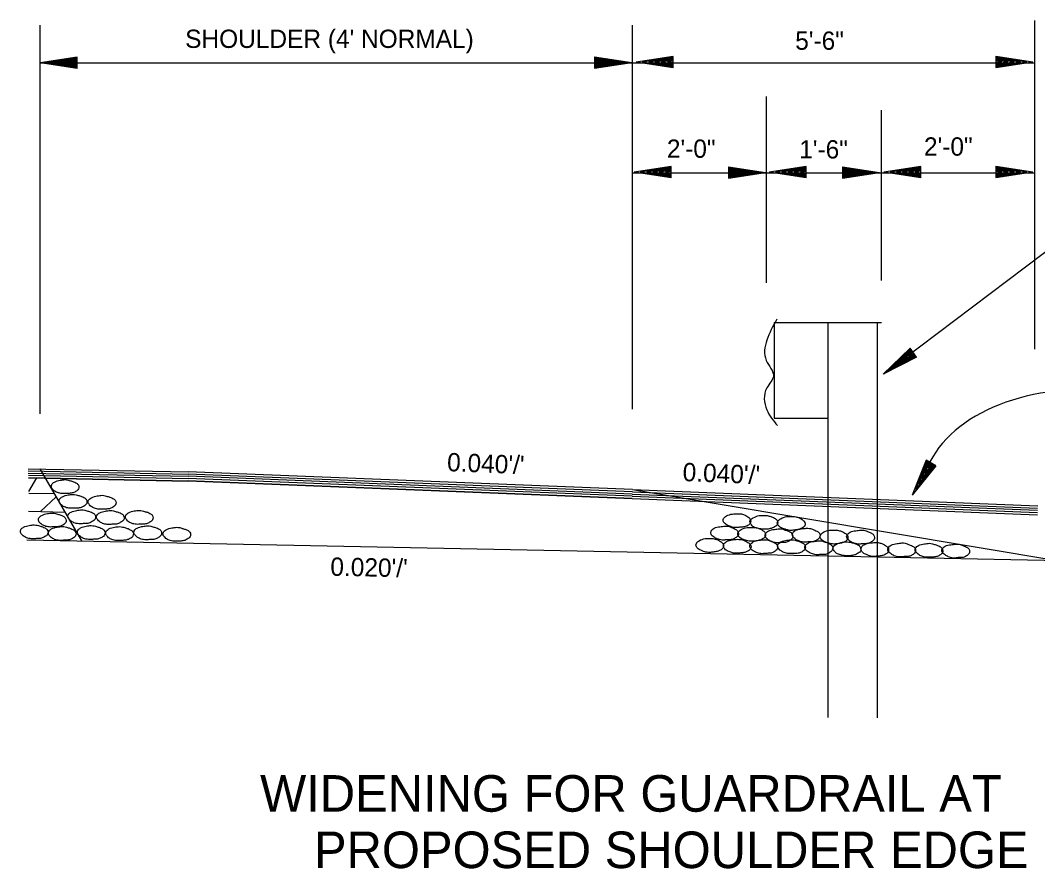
# Model space of a CAD drawing. Extents: x 3314 to 1767681, y -207 to 581440.
# Drawn here: x 3447.3 to 3514, y -206.8 to -151.2 of the extents above; entities that cross this region are included whole.
import ezdxf

# ---------------------------------------------------------------- set-up
doc = ezdxf.new("R2010")
doc.units = 0
doc.layers.add('Default', color=7, linetype='Continuous')

msp = doc.modelspace()

# ---------------------------------------------------------------- linework, layer by layer
at = {"layer": 'Default'}
for p, q in [((3448.572, -177.002), (3448.572, -151.494)), ((3487.452, -176.688), (3487.452, -151.494)), ((3513.862, -172.76), (3513.862, -151.181)), ((3484.969, -153.574), (3487.404, -153.943)), ((3484.969, -153.574), (3484.969, -154.308)), ((3490.125, -153.555), (3487.69, -153.919)), ((3490.125, -154.288), (3490.125, -153.555)), ((3511.305, -153.53), (3513.74, -153.9)), ((3511.305, -153.53), (3511.305, -154.264)), ((3451.007, -153.598), (3448.572, -153.963)), ((3448.572, -153.963), (3513.862, -153.963)), ((3451.007, -154.332), (3448.572, -153.963)), ((3451.007, -153.662), (3448.981, -153.963)), ((3451.007, -154.269), (3448.981, -153.963)), ((3451.007, -153.725), (3449.399, -153.963)), ((3451.007, -154.206), (3449.399, -153.963)), ((3451.007, -153.783), (3449.807, -153.963)), ((3451.007, -154.148), (3449.807, -153.963)), ((3451.007, -153.846), (3450.215, -153.963)), ((3451.007, -154.084), (3450.215, -153.963)), ((3451.007, -153.909), (3450.623, -153.963)), ((3451.007, -154.021), (3450.623, -153.963)), ((3451.007, -154.332), (3451.007, -153.598)), ((3484.969, -153.637), (3486.995, -153.943)), ((3484.969, -153.7), (3486.578, -153.943)), ((3484.969, -153.759), (3486.169, -153.943)), ((3484.969, -153.822), (3485.761, -153.943)), ((3484.969, -153.885), (3485.353, -153.943)), ((3484.969, -154.308), (3487.404, -153.943)), ((3484.969, -154.06), (3485.761, -153.943)), ((3484.969, -154.182), (3486.578, -153.943)), ((3484.969, -154.245), (3486.995, -153.943)), ((3484.969, -154.123), (3486.169, -153.943)), ((3484.969, -153.997), (3485.353, -153.943)), ((3490.125, -154.288), (3487.69, -153.919)), ((3490.125, -153.618), (3488.099, -153.919)), ((3490.125, -154.225), (3488.099, -153.919)), ((3490.125, -153.681), (3488.517, -153.919)), ((3490.125, -154.162), (3488.517, -153.919)), ((3490.125, -153.739), (3488.925, -153.919)), ((3490.125, -154.104), (3488.925, -153.919)), ((3490.125, -153.802), (3489.333, -153.919)), ((3490.125, -154.041), (3489.333, -153.919)), ((3490.125, -153.866), (3489.741, -153.919)), ((3490.125, -153.977), (3489.741, -153.919)), ((3511.305, -153.593), (3513.332, -153.9)), ((3511.305, -153.657), (3512.914, -153.9)), ((3511.305, -153.715), (3512.506, -153.9)), ((3511.305, -153.778), (3512.097, -153.9)), ((3511.305, -153.841), (3511.689, -153.9)), ((3511.305, -154.264), (3513.74, -153.9)), ((3511.305, -154.016), (3512.097, -153.9)), ((3511.305, -154.138), (3512.914, -153.9)), ((3511.305, -154.201), (3513.332, -153.9)), ((3511.305, -154.079), (3512.506, -153.9)), ((3511.305, -153.953), (3511.689, -153.9)), ((3496.254, -168.395), (3496.254, -156.174)), ((3503.801, -168.237), (3503.801, -157.064)), ((3489.994, -160.777), (3487.559, -161.141)), ((3489.994, -160.84), (3487.967, -161.141)), ((3489.994, -160.903), (3488.385, -161.141)), ((3489.994, -161.51), (3489.994, -160.777)), ((3493.751, -160.801), (3496.186, -161.17)), ((3493.751, -160.801), (3493.751, -161.535)), ((3493.751, -160.864), (3495.778, -161.17)), ((3498.864, -160.777), (3496.429, -161.141)), ((3498.864, -160.84), (3496.837, -161.141)), ((3498.864, -160.903), (3497.255, -161.141)), ((3498.864, -161.51), (3498.864, -160.777)), ((3501.23, -160.796), (3503.665, -161.165)), ((3501.23, -160.796), (3501.23, -161.53)), ((3501.23, -160.859), (3503.257, -161.165)), ((3506.387, -160.772), (3503.952, -161.136)), ((3506.387, -160.835), (3504.36, -161.136)), ((3506.387, -160.898), (3504.778, -161.136)), ((3506.387, -161.506), (3506.387, -160.772)), ((3511.305, -160.757), (3513.74, -161.126)), ((3511.305, -160.757), (3511.305, -161.491)), ((3511.305, -160.82), (3513.332, -161.126)), ((3511.305, -160.883), (3512.914, -161.126)), ((3487.452, -161.185), (3513.862, -161.185)), ((3489.994, -161.51), (3487.559, -161.141)), ((3489.994, -161.447), (3487.967, -161.141)), ((3489.994, -161.384), (3488.385, -161.141)), ((3489.994, -160.961), (3488.794, -161.141)), ((3489.994, -161.326), (3488.794, -161.141)), ((3489.994, -161.024), (3489.202, -161.141)), ((3489.994, -161.263), (3489.202, -161.141)), ((3489.994, -161.088), (3489.61, -161.141)), ((3489.994, -161.199), (3489.61, -161.141)), ((3493.751, -160.927), (3495.36, -161.17)), ((3493.751, -160.986), (3494.951, -161.17)), ((3493.751, -161.049), (3494.543, -161.17)), ((3493.751, -161.112), (3494.135, -161.17)), ((3493.751, -161.535), (3496.186, -161.17)), ((3493.751, -161.287), (3494.543, -161.17)), ((3493.751, -161.408), (3495.36, -161.17)), ((3493.751, -161.472), (3495.778, -161.17)), ((3493.751, -161.35), (3494.951, -161.17)), ((3493.751, -161.224), (3494.135, -161.17)), ((3498.864, -161.51), (3496.429, -161.141)), ((3498.864, -161.447), (3496.837, -161.141)), ((3498.864, -161.384), (3497.255, -161.141)), ((3498.864, -160.961), (3497.663, -161.141)), ((3498.864, -161.326), (3497.663, -161.141)), ((3498.864, -161.024), (3498.071, -161.141)), ((3498.864, -161.263), (3498.071, -161.141)), ((3498.864, -161.088), (3498.48, -161.141)), ((3498.864, -161.199), (3498.48, -161.141)), ((3501.23, -160.922), (3502.839, -161.165)), ((3501.23, -160.981), (3502.431, -161.165)), ((3501.23, -161.044), (3502.023, -161.165)), ((3501.23, -161.107), (3501.614, -161.165)), ((3501.23, -161.53), (3503.665, -161.165)), ((3501.23, -161.282), (3502.023, -161.165)), ((3501.23, -161.404), (3502.839, -161.165)), ((3501.23, -161.467), (3503.257, -161.165)), ((3501.23, -161.345), (3502.431, -161.165)), ((3501.23, -161.219), (3501.614, -161.165)), ((3506.387, -161.506), (3503.952, -161.136)), ((3506.387, -161.442), (3504.36, -161.136)), ((3506.387, -161.379), (3504.778, -161.136)), ((3506.387, -160.956), (3505.186, -161.136)), ((3506.387, -161.321), (3505.186, -161.136)), ((3506.387, -161.02), (3505.595, -161.136)), ((3506.387, -161.258), (3505.595, -161.136)), ((3506.387, -161.083), (3506.003, -161.136)), ((3506.387, -161.195), (3506.003, -161.136)), ((3511.305, -160.942), (3512.506, -161.126)), ((3511.305, -161.005), (3512.097, -161.126)), ((3511.305, -161.068), (3511.689, -161.126)), ((3511.305, -161.491), (3513.74, -161.126)), ((3511.305, -161.243), (3512.097, -161.126)), ((3511.305, -161.365), (3512.914, -161.126)), ((3511.305, -161.428), (3513.332, -161.126)), ((3511.305, -161.306), (3512.506, -161.126)), ((3511.305, -161.18), (3511.689, -161.126)), ((3503.962, -174.355), (3517.652, -164.008)), ((3496.759, -170.997), (3496.759, -177.286)), ((3496.759, -170.997), (3503.801, -170.997)), ((3500.283, -170.997), (3500.283, -196.911)), ((3503.519, -171.026), (3503.519, -196.935)), ((3505.689, -172.693), (3503.899, -174.383)), ((3505.728, -172.74), (3504.231, -174.155)), ((3505.766, -172.799), (3504.585, -173.903)), ((3505.791, -172.849), (3504.914, -173.675)), ((3505.828, -172.891), (3505.245, -173.442)), ((3506.102, -173.286), (3505.689, -172.693)), ((3506.102, -173.286), (3503.899, -174.383)), ((3506.073, -173.241), (3504.231, -174.155)), ((3506.029, -173.187), (3504.585, -173.903)), ((3505.995, -173.136), (3504.914, -173.675)), ((3505.956, -173.082), (3505.245, -173.442)), ((3505.862, -172.944), (3505.582, -173.207)), ((3505.932, -173.027), (3505.582, -173.207)), ((3496.759, -177.286), (3500.283, -177.286)), ((3506.722, -180.037), (3505.818, -182.331)), ((3506.771, -180.076), (3506.022, -181.976)), ((3506.829, -180.105), (3506.231, -181.611)), ((3506.878, -180.134), (3506.431, -181.266)), ((3506.936, -180.163), (3506.64, -180.907)), ((3507.354, -180.406), (3506.722, -180.037)), ((3506.994, -180.197), (3506.849, -180.557)), ((3507.087, -180.251), (3506.849, -180.557)), ((3447.79, -180.591), (3458.292, -180.8)), ((3447.79, -180.737), (3458.292, -180.946)), ((3447.795, -180.882), (3458.292, -181.091)), ((3451.304, -185.329), (3448.572, -180.607)), ((3487.452, -181.966), (3458.292, -180.8)), ((3487.452, -182.112), (3458.292, -180.946)), ((3507.354, -180.406), (3505.818, -182.331)), ((3507.305, -180.372), (3506.022, -181.976)), ((3507.242, -180.348), (3506.231, -181.611)), ((3507.194, -180.314), (3506.431, -181.266)), ((3507.14, -180.285), (3506.64, -180.907)), ((3447.8, -181.028), (3458.292, -181.237)), ((3447.804, -181.174), (3458.283, -181.383)), ((3447.804, -181.193), (3458.292, -181.402)), ((3447.824, -182.078), (3448.349, -181.198)), ((3487.433, -182.549), (3458.273, -181.383)), ((3487.443, -182.258), (3458.283, -181.091)), ((3487.443, -182.404), (3458.283, -181.237)), ((3487.433, -182.569), (3458.292, -181.402)), ((3447.829, -182.195), (3449.51, -182.229)), ((3487.439, -182.258), (3514.038, -183.322)), ((3487.444, -182.112), (3514.043, -183.176)), ((3487.452, -181.966), (3514.051, -183.031)), ((3487.452, -181.966), (3534.38, -189.791)), ((3448.592, -183.405), (3449.625, -182.428)), ((3487.428, -182.549), (3514.027, -183.614)), ((3487.433, -182.404), (3514.032, -183.468)), ((3447.804, -183.389), (3450.209, -183.437)), ((3447.694, -185.256), (3525.399, -186.802))]:
    msp.add_line(p, q, dxfattribs=at)
msp.add_ellipse((3518.439, -183.401), major_axis=(-12.01, 1.466), ratio=0.655798, start_param=4.712389, end_param=6.093533, dxfattribs=at)
for points in [[(3496.929, -170.793), (3496.268, -172.159), (3496.234, -173.49), (3496.711, -174.516), (3496.268, -175.293), (3496.268, -176.727), (3496.968, -177.762)], [(3450.207, -181.312), (3449.886, -181.351), (3449.517, -181.467), (3449.332, -181.632), (3449.303, -181.749), (3449.39, -181.943), (3449.497, -182.041), (3449.711, -182.157), (3450.022, -182.225), (3450.178, -182.225), (3450.421, -182.216), (3450.683, -182.186), (3450.897, -182.099), (3451.091, -181.924), (3451.121, -181.807), (3451.062, -181.632), (3450.916, -181.516), (3450.771, -181.448), (3450.557, -181.38), (3450.411, -181.341), (3450.207, -181.312)], [(3450.735, -182.277), (3450.414, -182.316), (3450.045, -182.433), (3449.851, -182.598), (3449.821, -182.715), (3449.909, -182.909), (3450.016, -183.006), (3450.23, -183.123), (3450.541, -183.191), (3450.706, -183.191), (3450.949, -183.181), (3451.211, -183.152), (3451.415, -183.065), (3451.62, -182.89), (3451.649, -182.773), (3451.59, -182.598), (3451.445, -182.481), (3451.299, -182.413), (3451.075, -182.345), (3450.939, -182.306), (3450.735, -182.277)], [(3452.643, -182.34), (3452.323, -182.379), (3451.953, -182.496), (3451.759, -182.661), (3451.73, -182.778), (3451.817, -182.972), (3451.924, -183.069), (3452.138, -183.186), (3452.449, -183.254), (3452.614, -183.254), (3452.857, -183.244), (3453.12, -183.215), (3453.324, -183.128), (3453.528, -182.953), (3453.557, -182.836), (3453.499, -182.661), (3453.353, -182.545), (3453.207, -182.476), (3452.984, -182.408), (3452.848, -182.37), (3452.643, -182.34)], [(3449.371, -183.504), (3449.05, -183.542), (3448.681, -183.659), (3448.496, -183.824), (3448.467, -183.941), (3448.555, -184.135), (3448.661, -184.233), (3448.875, -184.349), (3449.186, -184.417), (3449.342, -184.417), (3449.585, -184.408), (3449.847, -184.378), (3450.061, -184.291), (3450.256, -184.116), (3450.285, -183.999), (3450.226, -183.824), (3450.081, -183.708), (3449.935, -183.64), (3449.721, -183.572), (3449.575, -183.533), (3449.371, -183.504)], [(3451.3, -183.288), (3450.98, -183.327), (3450.61, -183.444), (3450.416, -183.609), (3450.387, -183.716), (3450.474, -183.91), (3450.581, -184.017), (3450.795, -184.134), (3451.106, -184.202), (3451.271, -184.202), (3451.514, -184.192), (3451.777, -184.163), (3451.981, -184.066), (3452.185, -183.9), (3452.214, -183.774), (3452.156, -183.599), (3452.01, -183.482), (3451.864, -183.414), (3451.641, -183.356), (3451.505, -183.308), (3451.3, -183.288)], [(3453.18, -183.332), (3452.859, -183.371), (3452.489, -183.487), (3452.295, -183.653), (3452.266, -183.76), (3452.353, -183.954), (3452.46, -184.061), (3452.674, -184.177), (3452.985, -184.246), (3453.15, -184.246), (3453.393, -184.236), (3453.656, -184.207), (3453.86, -184.109), (3454.064, -183.944), (3454.093, -183.818), (3454.035, -183.643), (3453.889, -183.526), (3453.743, -183.458), (3453.52, -183.4), (3453.384, -183.351), (3453.18, -183.332)], [(3455.072, -183.329), (3454.751, -183.367), (3454.382, -183.484), (3454.197, -183.649), (3454.168, -183.756), (3454.255, -183.951), (3454.362, -184.058), (3454.576, -184.174), (3454.887, -184.242), (3455.043, -184.242), (3455.286, -184.233), (3455.548, -184.203), (3455.762, -184.106), (3455.956, -183.941), (3455.985, -183.815), (3455.927, -183.64), (3455.781, -183.523), (3455.636, -183.455), (3455.422, -183.397), (3455.276, -183.348), (3455.072, -183.329)], [(3494.339, -183.549), (3494.018, -183.568), (3493.629, -183.685), (3493.425, -183.87), (3493.396, -183.977), (3493.493, -184.171), (3493.61, -184.258), (3493.834, -184.365), (3494.145, -184.453), (3494.31, -184.453), (3494.543, -184.433), (3494.806, -184.404), (3495.01, -184.327), (3495.185, -184.161), (3495.214, -184.035), (3495.155, -183.86), (3495.029, -183.743), (3494.893, -183.666), (3494.679, -183.578), (3494.543, -183.549), (3494.339, -183.549)], [(3448.18, -184.276), (3447.86, -184.315), (3447.49, -184.432), (3447.305, -184.597), (3447.276, -184.714), (3447.364, -184.908), (3447.471, -185.005), (3447.685, -185.122), (3447.996, -185.19), (3448.151, -185.19), (3448.394, -185.18), (3448.657, -185.151), (3448.87, -185.064), (3449.065, -184.889), (3449.094, -184.772), (3449.036, -184.597), (3448.89, -184.48), (3448.744, -184.412), (3448.53, -184.344), (3448.384, -184.305), (3448.18, -184.276)], [(3496.08, -183.653), (3495.76, -183.672), (3495.381, -183.808), (3495.186, -183.964), (3495.157, -184.071), (3495.264, -184.275), (3495.351, -184.382), (3495.585, -184.479), (3495.876, -184.547), (3496.042, -184.566), (3496.285, -184.557), (3496.557, -184.508), (3496.751, -184.42), (3496.955, -184.265), (3496.984, -184.139), (3496.926, -183.964), (3496.78, -183.837), (3496.634, -183.769), (3496.421, -183.701), (3496.285, -183.672), (3496.08, -183.653)], [(3497.893, -183.725), (3497.572, -183.735), (3497.184, -183.871), (3496.989, -184.046), (3496.96, -184.163), (3497.067, -184.357), (3497.174, -184.445), (3497.388, -184.542), (3497.699, -184.629), (3497.864, -184.639), (3498.097, -184.62), (3498.36, -184.571), (3498.564, -184.493), (3498.758, -184.338), (3498.787, -184.221), (3498.729, -184.046), (3498.583, -183.93), (3498.447, -183.832), (3498.233, -183.764), (3498.097, -183.735), (3497.893, -183.725)], [(3450.019, -184.382), (3449.698, -184.42), (3449.329, -184.537), (3449.144, -184.702), (3449.115, -184.819), (3449.203, -185.013), (3449.309, -185.111), (3449.523, -185.227), (3449.834, -185.295), (3449.99, -185.295), (3450.233, -185.286), (3450.495, -185.256), (3450.709, -185.169), (3450.904, -184.994), (3450.933, -184.877), (3450.874, -184.702), (3450.729, -184.586), (3450.583, -184.518), (3450.369, -184.45), (3450.223, -184.411), (3450.019, -184.382)], [(3451.924, -184.318), (3451.603, -184.357), (3451.234, -184.474), (3451.049, -184.639), (3451.02, -184.756), (3451.108, -184.95), (3451.215, -185.047), (3451.428, -185.164), (3451.739, -185.232), (3451.895, -185.232), (3452.138, -185.222), (3452.4, -185.193), (3452.614, -185.106), (3452.809, -184.931), (3452.838, -184.814), (3452.779, -184.639), (3452.634, -184.523), (3452.488, -184.454), (3452.274, -184.386), (3452.128, -184.348), (3451.924, -184.318)], [(3453.781, -184.39), (3453.46, -184.429), (3453.091, -184.545), (3452.906, -184.71), (3452.877, -184.827), (3452.964, -185.021), (3453.071, -185.119), (3453.285, -185.235), (3453.596, -185.303), (3453.751, -185.303), (3453.994, -185.294), (3454.257, -185.264), (3454.471, -185.177), (3454.665, -185.002), (3454.694, -184.885), (3454.636, -184.71), (3454.49, -184.594), (3454.344, -184.526), (3454.131, -184.458), (3453.985, -184.419), (3453.781, -184.39)], [(3455.632, -184.338), (3455.312, -184.377), (3454.942, -184.493), (3454.757, -184.659), (3454.728, -184.766), (3454.816, -184.96), (3454.923, -185.067), (3455.137, -185.183), (3455.448, -185.252), (3455.603, -185.252), (3455.846, -185.242), (3456.109, -185.213), (3456.322, -185.115), (3456.517, -184.95), (3456.546, -184.824), (3456.488, -184.649), (3456.342, -184.532), (3456.196, -184.464), (3455.982, -184.406), (3455.836, -184.357), (3455.632, -184.338)], [(3457.537, -184.438), (3457.217, -184.477), (3456.847, -184.594), (3456.663, -184.759), (3456.633, -184.866), (3456.721, -185.06), (3456.828, -185.167), (3457.042, -185.284), (3457.353, -185.352), (3457.508, -185.352), (3457.751, -185.342), (3458.014, -185.313), (3458.228, -185.216), (3458.422, -185.051), (3458.451, -184.924), (3458.393, -184.749), (3458.247, -184.633), (3458.101, -184.565), (3457.887, -184.506), (3457.742, -184.458), (3457.537, -184.438)], [(3493.534, -184.361), (3493.194, -184.399), (3492.815, -184.497), (3492.62, -184.681), (3492.591, -184.788), (3492.688, -184.992), (3492.805, -185.08), (3493.019, -185.196), (3493.33, -185.274), (3493.485, -185.274), (3493.728, -185.255), (3494, -185.235), (3494.204, -185.138), (3494.379, -184.973), (3494.409, -184.847), (3494.35, -184.672), (3494.204, -184.555), (3494.068, -184.497), (3493.855, -184.409), (3493.728, -184.37), (3493.534, -184.361)], [(3495.298, -184.443), (3494.977, -184.453), (3494.588, -184.579), (3494.394, -184.764), (3494.365, -184.871), (3494.472, -185.075), (3494.579, -185.162), (3494.793, -185.26), (3495.104, -185.337), (3495.269, -185.357), (3495.502, -185.337), (3495.765, -185.289), (3495.969, -185.211), (3496.163, -185.056), (3496.192, -184.929), (3496.134, -184.754), (3495.988, -184.638), (3495.852, -184.55), (3495.638, -184.482), (3495.502, -184.453), (3495.298, -184.443)], [(3497.095, -184.542), (3496.774, -184.571), (3496.385, -184.678), (3496.181, -184.863), (3496.152, -184.97), (3496.259, -185.164), (3496.366, -185.252), (3496.589, -185.378), (3496.89, -185.446), (3497.056, -185.446), (3497.289, -185.426), (3497.571, -185.417), (3497.765, -185.32), (3497.95, -185.154), (3497.979, -185.028), (3497.921, -184.853), (3497.785, -184.736), (3497.639, -184.668), (3497.435, -184.6), (3497.299, -184.542), (3497.095, -184.542)], [(3498.864, -184.497), (3498.543, -184.535), (3498.164, -184.633), (3497.969, -184.817), (3497.94, -184.924), (3498.047, -185.128), (3498.154, -185.216), (3498.368, -185.333), (3498.679, -185.41), (3498.834, -185.41), (3499.077, -185.391), (3499.34, -185.371), (3499.554, -185.274), (3499.738, -185.109), (3499.768, -184.983), (3499.709, -184.808), (3499.563, -184.691), (3499.418, -184.633), (3499.214, -184.535), (3499.068, -184.506), (3498.864, -184.497)], [(3500.701, -184.623), (3500.38, -184.633), (3499.991, -184.759), (3499.797, -184.944), (3499.768, -185.051), (3499.874, -185.255), (3499.981, -185.342), (3500.195, -185.439), (3500.506, -185.517), (3500.672, -185.537), (3500.905, -185.517), (3501.167, -185.469), (3501.371, -185.391), (3501.566, -185.235), (3501.595, -185.109), (3501.537, -184.934), (3501.391, -184.817), (3501.255, -184.73), (3501.041, -184.662), (3500.905, -184.633), (3500.701, -184.623)], [(3502.432, -184.623), (3502.112, -184.662), (3501.733, -184.759), (3501.538, -184.944), (3501.509, -185.051), (3501.616, -185.255), (3501.723, -185.342), (3501.937, -185.459), (3502.248, -185.537), (3502.403, -185.537), (3502.646, -185.517), (3502.909, -185.498), (3503.123, -185.401), (3503.307, -185.235), (3503.336, -185.109), (3503.278, -184.934), (3503.132, -184.817), (3502.987, -184.759), (3502.782, -184.662), (3502.637, -184.633), (3502.432, -184.623)], [(3492.542, -185.169), (3492.222, -185.179), (3491.833, -185.315), (3491.648, -185.49), (3491.619, -185.606), (3491.716, -185.801), (3491.833, -185.888), (3492.037, -185.985), (3492.358, -186.073), (3492.513, -186.083), (3492.756, -186.063), (3493.019, -186.015), (3493.223, -185.937), (3493.407, -185.781), (3493.437, -185.665), (3493.378, -185.49), (3493.232, -185.373), (3493.096, -185.276), (3492.883, -185.208), (3492.746, -185.179), (3492.542, -185.169)], [(3494.341, -185.226), (3494.02, -185.255), (3493.631, -185.371), (3493.446, -185.546), (3493.417, -185.663), (3493.514, -185.857), (3493.612, -185.945), (3493.835, -186.042), (3494.136, -186.139), (3494.302, -186.139), (3494.545, -186.12), (3494.817, -186.081), (3495.011, -186.013), (3495.206, -185.838), (3495.235, -185.721), (3495.176, -185.546), (3495.031, -185.43), (3494.885, -185.342), (3494.681, -185.264), (3494.545, -185.235), (3494.341, -185.226)], [(3496.089, -185.252), (3495.768, -185.29), (3495.379, -185.397), (3495.185, -185.572), (3495.155, -185.689), (3495.262, -185.883), (3495.369, -185.971), (3495.583, -186.087), (3495.884, -186.165), (3496.05, -186.165), (3496.293, -186.146), (3496.555, -186.126), (3496.759, -186.039), (3496.954, -185.864), (3496.983, -185.747), (3496.924, -185.572), (3496.779, -185.456), (3496.633, -185.388), (3496.419, -185.31), (3496.293, -185.261), (3496.089, -185.252)], [(3497.918, -185.25), (3497.587, -185.289), (3497.198, -185.396), (3497.004, -185.571), (3496.975, -185.687), (3497.082, -185.882), (3497.189, -185.969), (3497.412, -186.096), (3497.713, -186.164), (3497.869, -186.164), (3498.112, -186.154), (3498.384, -186.125), (3498.588, -186.037), (3498.773, -185.862), (3498.802, -185.746), (3498.744, -185.571), (3498.598, -185.454), (3498.452, -185.386), (3498.248, -185.318), (3498.122, -185.279), (3497.918, -185.25)], [(3499.709, -185.323), (3499.369, -185.362), (3499, -185.459), (3498.796, -185.644), (3498.766, -185.75), (3498.873, -185.955), (3498.98, -186.042), (3499.204, -186.159), (3499.505, -186.236), (3499.661, -186.236), (3499.904, -186.217), (3500.186, -186.198), (3500.38, -186.1), (3500.565, -185.935), (3500.594, -185.809), (3500.535, -185.634), (3500.39, -185.517), (3500.254, -185.459), (3500.04, -185.381), (3499.913, -185.333), (3499.709, -185.323)], [(3501.541, -185.397), (3501.221, -185.417), (3500.842, -185.553), (3500.647, -185.708), (3500.618, -185.815), (3500.725, -186.019), (3500.812, -186.126), (3501.046, -186.224), (3501.337, -186.292), (3501.503, -186.311), (3501.746, -186.301), (3502.018, -186.253), (3502.212, -186.165), (3502.416, -186.01), (3502.445, -185.883), (3502.387, -185.708), (3502.241, -185.582), (3502.096, -185.514), (3501.882, -185.446), (3501.746, -185.417), (3501.541, -185.397)], [(3503.369, -185.435), (3503.048, -185.464), (3502.659, -185.58), (3502.475, -185.755), (3502.445, -185.872), (3502.543, -186.066), (3502.64, -186.154), (3502.863, -186.251), (3503.165, -186.348), (3503.33, -186.348), (3503.573, -186.329), (3503.845, -186.29), (3504.04, -186.222), (3504.234, -186.047), (3504.263, -185.93), (3504.205, -185.755), (3504.059, -185.639), (3503.913, -185.551), (3503.709, -185.473), (3503.573, -185.444), (3503.369, -185.435)], [(3505.143, -185.464), (3504.822, -185.503), (3504.433, -185.61), (3504.239, -185.785), (3504.21, -185.901), (3504.317, -186.096), (3504.423, -186.183), (3504.637, -186.3), (3504.939, -186.377), (3505.104, -186.377), (3505.347, -186.358), (3505.609, -186.339), (3505.813, -186.251), (3506.008, -186.076), (3506.037, -185.959), (3505.979, -185.785), (3505.833, -185.668), (3505.687, -185.6), (3505.473, -185.522), (3505.347, -185.473), (3505.143, -185.464)], [(3506.943, -185.488), (3506.612, -185.527), (3506.223, -185.634), (3506.029, -185.809), (3506, -185.925), (3506.107, -186.12), (3506.214, -186.207), (3506.437, -186.334), (3506.738, -186.402), (3506.894, -186.402), (3507.137, -186.392), (3507.409, -186.363), (3507.613, -186.275), (3507.798, -186.1), (3507.827, -185.984), (3507.769, -185.809), (3507.623, -185.692), (3507.477, -185.624), (3507.273, -185.556), (3507.147, -185.517), (3506.943, -185.488)], [(3508.697, -185.538), (3508.357, -185.577), (3507.978, -185.674), (3507.783, -185.859), (3507.754, -185.966), (3507.861, -186.16), (3507.968, -186.248), (3508.182, -186.364), (3508.493, -186.452), (3508.648, -186.452), (3508.891, -186.423), (3509.164, -186.413), (3509.368, -186.316), (3509.552, -186.151), (3509.582, -186.024), (3509.523, -185.849), (3509.377, -185.733), (3509.232, -185.665), (3509.027, -185.587), (3508.891, -185.548), (3508.697, -185.538)]]:
    msp.add_spline(points, degree=3, dxfattribs=at)

# ---------------------------------------------------------------- texts
for s, height, p in [("SHOULDER (4' NORMAL)", 1.2, (3458.095, -152.99)), ('5\'-6"', 1.2, (3498.135, -153.112)), ('2\'-0"', 1.2, (3506.586, -160.057)), ('2\'-0"', 1.2, (3489.712, -160.198)), ('1\'-6"', 1.2, (3498.397, -160.242)), ('WIDENING FOR GUARDRAIL AT ', 2.4, (3463.01, -203.095)), ('PROPOSED SHOULDER EDGE', 2.4, (3466.548, -206.795))]:
    msp.add_text(s, height=height, dxfattribs=at).set_placement(p)
for s, rotation, p in [("0.040'/'", 357.70939, (3475.268, -180.75)), ("0.040'/'", 357.70939, (3490.727, -181.401)), ("0.020'/'", 358.8537, (3467.614, -187.613))]:
    msp.add_text(s, height=1.2, rotation=rotation, dxfattribs=at).set_placement(p)

doc.saveas('drawing.dxf')
